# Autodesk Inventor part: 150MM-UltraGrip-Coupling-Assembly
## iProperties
Created: 2012-05
Part Number: 150MM-UltraGrip-Coupling-Assembly
Document SubType Name: Modeling
Designer: D Cole
Density: 1 g/cm^3
Author: D Cole
